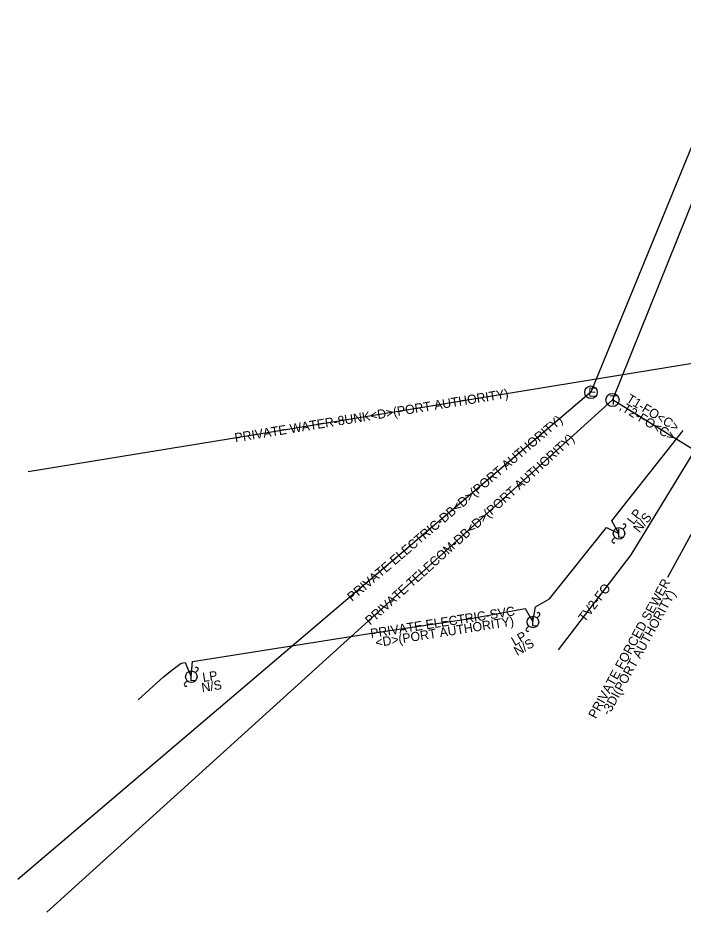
# Model space of a CAD drawing. Extents: x 2336688 to 2352634, y 362473 to 369571.
# Drawn here: x 2345105.3 to 2345394.9, y 366720.6 to 367109.6 of the extents above; entities that cross this region are included whole.
import ezdxf

# ---------------------------------------------------------------- set-up
doc = ezdxf.new("R2010")
doc.units = 0
for name, color, linetype in [('RD_EX_DV_Prop', 7, 'Continuous'), ('RD_EX_DV_TX_Prop', 7, 'Continuous'), ('RD_EX_RW', 7, 'Continuous'), ('RD_EX_RW_TX', 7, 'Continuous'), ('RD_HC_Data_Tic', 7, 'Continuous'), ('RD_PD_CstnLmt', 7, 'Continuous'), ('RD_PD_Final_TrvlWay', 7, 'Continuous'), ('RD_Sketch1', 7, 'Continuous'), ('RD_Sketch2', 7, 'Continuous'), ('RD_Sketch5', 7, 'Continuous')]:
    doc.layers.add(name, color=color, linetype=linetype)

msp = doc.modelspace()

# ---------------------------------------------------------------- linework, layer by layer
at = {"layer": 'RD_EX_RW_TX'}
msp.add_line((2345399.69, 366921.53), (2345364.16, 366943.34), dxfattribs=at)
for points in [[(2345400.86, 367609.96), (2345400.86, 367580.52), (2345476.19, 367221.38), (2345364.16, 366943.34), (2345117.95, 366720.57)], [(2345560.36, 367158.37), (2345561.17, 367156.84), (2345555.2, 367151.92), (2345529.41, 367128.95), (2345527.05, 367109.15), (2345521, 367081.68), (2345512.82, 367070.16), (2345492.13, 367039.11), (2345457.71, 366999.28), (2345443.39, 366979.23), (2345436.01, 366963.6), (2345427.31, 366951.13), (2345399.42, 366920.61), (2345372.17, 366875.98), (2345340.52, 366834.69)]]:
    msp.add_lwpolyline(points, dxfattribs=at)
msp.add_circle((2345364.16, 366943.34), 2.89, dxfattribs=at)
at = {"layer": 'RD_HC_Data_Tic'}
for p, q in [((2345368.75, 366887.08), (2345369.81, 366888.14)), ((2345364.15, 366882.49), (2345365.21, 366883.55)), ((2345331.31, 366848.53), (2345332.37, 366849.59)), ((2345326.71, 366843.94), (2345327.77, 366845)), ((2345182.6, 366824.73), (2345183.66, 366825.79)), ((2345178, 366820.13), (2345179.06, 366821.19))]:
    msp.add_line(p, q, dxfattribs=at)
for centre in [(2345366.98, 366885.31), (2345329.54, 366846.77), (2345180.83, 366822.96)]:
    msp.add_circle(centre, 2.5, dxfattribs=at)
for centre, start, end in [((2345369.28, 366888.67), 315, 135), ((2345364.68, 366881.96), 135, 315), ((2345331.84, 366850.12), 315, 135), ((2345327.24, 366843.41), 135, 315), ((2345183.13, 366826.32), 315, 135), ((2345178.53, 366819.6), 135, 315)]:
    msp.add_arc(centre, 0.75, start, end, dxfattribs=at)
at = {"layer": 'RD_PD_Final_TrvlWay'}
for points in [[(2345391.05, 367609.96), (2345391.05, 367588.26), (2345470.9, 367229.85), (2345354.8, 366946.71), (2345105.35, 366734.78)], [(2345157.67, 366812.87), (2345164.05, 366818.65), (2345168.68, 366822.89), (2345172.96, 366826.29), (2345176.47, 366828.85), (2345178.18, 366829.12), (2345180.83, 366822.96), (2345181.31, 366829.61), (2345257.53, 366841.56), (2345303.35, 366848.37), (2345326.18, 366852.58), (2345329.54, 366846.77), (2345330.67, 366853.41), (2345336.73, 366856.9), (2345361.5, 366887.89), (2345366.98, 366885.31), (2345363.82, 366890.79), (2345370.88, 366899.63), (2345394.98, 366930.11)]]:
    msp.add_lwpolyline(points, dxfattribs=at)
msp.add_circle((2345354.8, 366946.71), 2.75, dxfattribs=at)
at = {"layer": 'RD_Sketch2'}
msp.add_lwpolyline([(2345109.82, 366912.24), (2345406.89, 366960.68), (2345406.94, 366978.47), (2345408.67, 367610.14)], dxfattribs=at)
at = {"layer": 'RD_Sketch5'}
msp.add_lwpolyline([(2345388.31, 366866.23), (2345411.68, 366909.13), (2345430.85, 366961.88), (2345435.05, 366988.91), (2345438.45, 367037.33), (2345442.85, 367076.95), (2345451.04, 367117.69)], dxfattribs=at)

# ---------------------------------------------------------------- texts
at = {"layer": 'RD_EX_DV_Prop'}
for s, rotation, p in [('PRIVATE ELECTRIC-DB<D>(PORT AUTHORITY)', 40.4256, (2345250.8, 366855.52)), ('PRIVATE ELECTRIC-SVC', 8.9832, (2345259.1, 366839.77)), ('<D>(PORT AUTHORITY)', 8.9832, (2345261.31, 366835.77))]:
    msp.add_text(s, height=4, rotation=rotation, dxfattribs=at).set_placement(p)
at = {"layer": 'RD_EX_DV_TX_Prop'}
for s, rotation, p in [('LP', 51.3676, (2345373.28, 366888.86)), ('N/S', 51.3676, (2345375.92, 366885.3)), ('LP', 29.9423, (2345321.56, 366836.2)), ('N/S', 29.9423, (2345322.72, 366831.93)), ('LP', 8.9154, (2345186.03, 366820.63)), ('N/S', 8.9154, (2345185.57, 366816.23))]:
    msp.add_text(s, height=4, rotation=rotation, dxfattribs=at).set_placement(p)
at = {"layer": 'RD_EX_RW'}
for s, rotation, p in [('T1-FO<C>', 328.4479, (2345369.82, 366942.78)), (',T2-FO<C>', 328.4479, (2345366.86, 366939.43)), ('PRIVATE TELECOM-DB<D>(PORT AUTHORITY)', 42.1384, (2345258.67, 366845.2)), ('TV2-FO', 52.5248, (2345352.07, 366846.46))]:
    msp.add_text(s, height=4, rotation=rotation, dxfattribs=at).set_placement(p)
at = {"layer": 'RD_EX_RW_TX'}
msp.add_text('T', height=4.12, dxfattribs=at).set_placement((2345362.83, 366941.28))
at = {"layer": 'RD_HC_Data_Tic'}
for p in [(2345366.17, 366883.38), (2345328.73, 366844.83), (2345180.02, 366821.03)]:
    msp.add_text('L', height=4, rotation=360, dxfattribs=at).set_placement(p)
at = {"layer": 'RD_PD_CstnLmt'}
msp.add_text('PRIVATE WATER-8UNK<D>(PORT AUTHORITY)', height=4, rotation=9.233, dxfattribs=at).set_placement((2345200.03, 366924.92))
at = {"layer": 'RD_PD_Final_TrvlWay'}
msp.add_text('E', height=3.93, dxfattribs=at).set_placement((2345353.61, 366944.75))
at = {"layer": 'RD_Sketch1'}
for s, p in [('PRIVATE FORCED SEWER', (2345356.91, 366804.42)), ('-3DI(PORT AUTHORITY)', (2345362.66, 366805.79))]:
    msp.add_text(s, height=4, rotation=61.4151, dxfattribs=at).set_placement(p)

doc.saveas('drawing.dxf')
